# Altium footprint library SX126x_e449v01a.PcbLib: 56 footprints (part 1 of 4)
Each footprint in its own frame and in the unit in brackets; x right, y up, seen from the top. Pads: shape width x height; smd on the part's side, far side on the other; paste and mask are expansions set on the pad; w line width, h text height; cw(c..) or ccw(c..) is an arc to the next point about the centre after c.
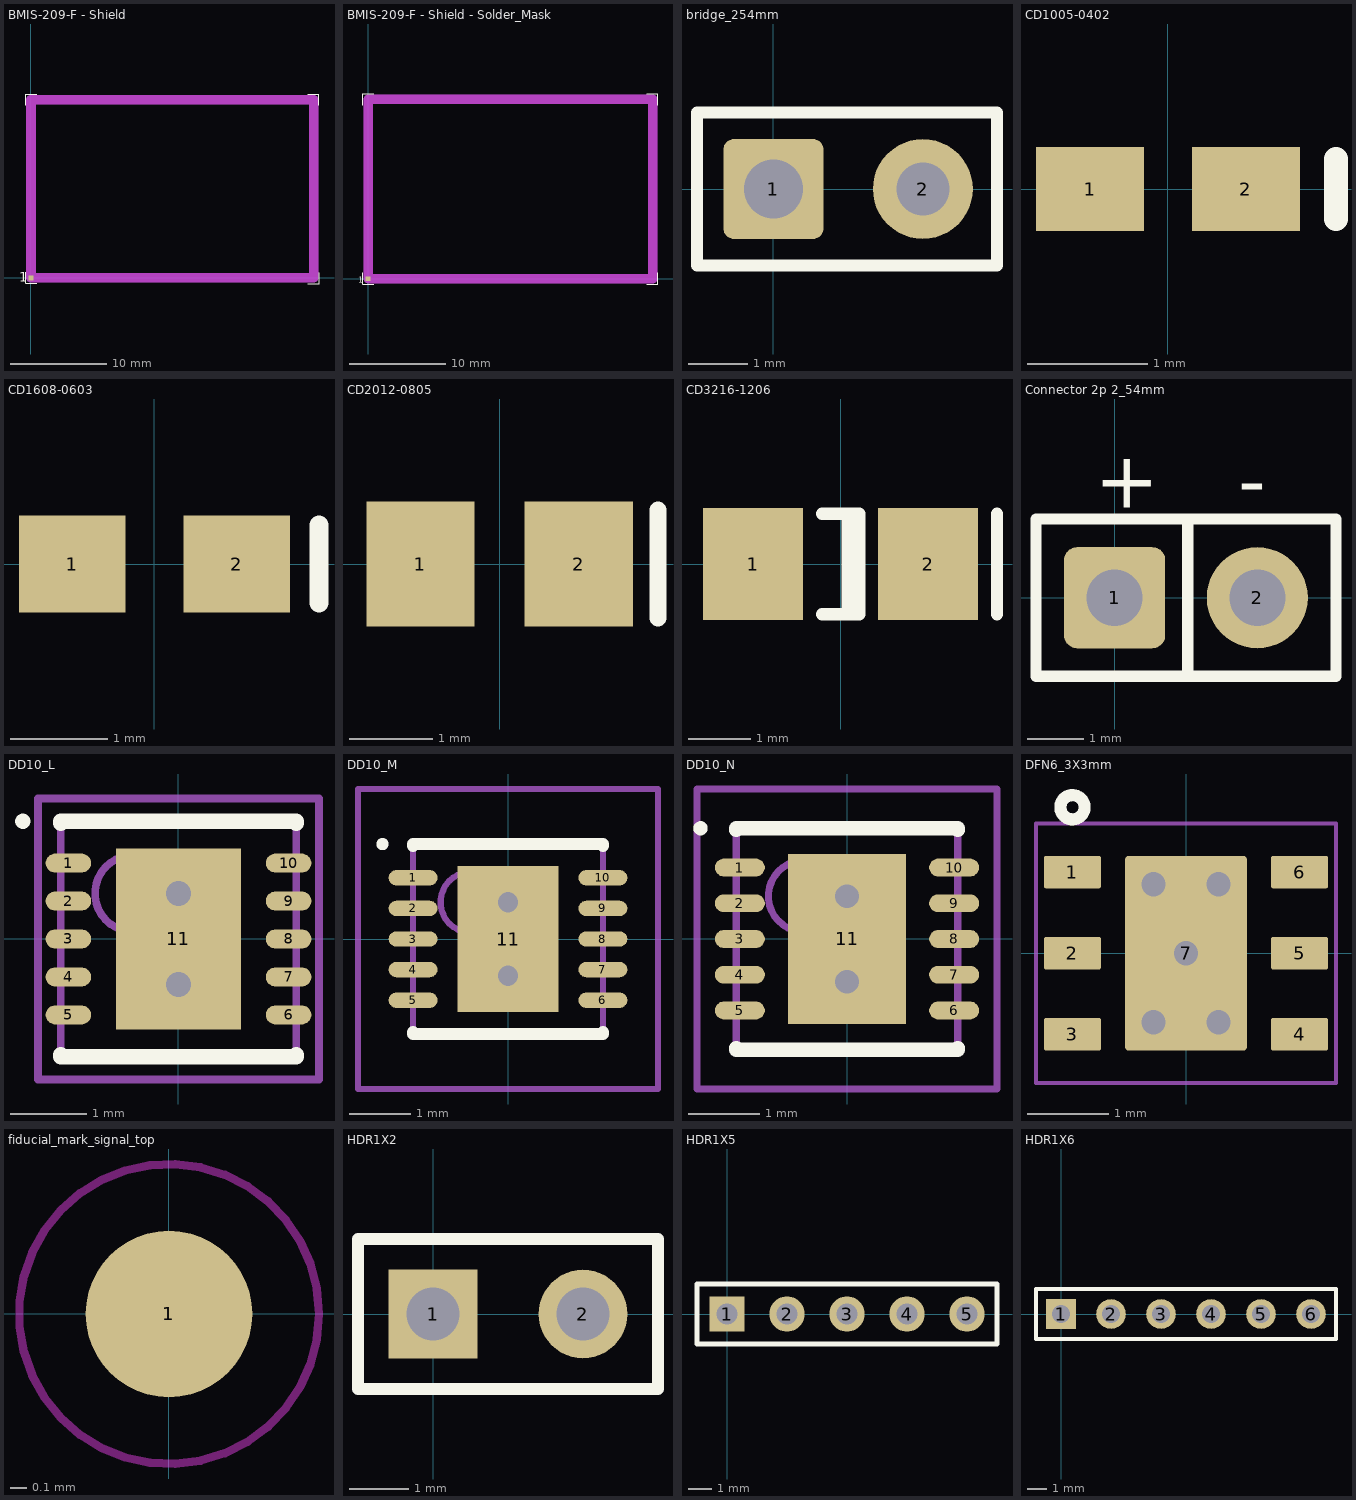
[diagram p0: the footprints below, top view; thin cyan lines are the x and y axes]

## BMIS-209-F - Shield [mm] "BMIS-209-F EMI Gasket - modif SolderMask - Standard Surface Mount Shields -  Laird Technologies"
height 6.5
pads (1):
  rect 0.5x0.5 smd paste-1 mask+0.05: 1(0,0)
Top Overlay:
  lines w0.1: -0.55,0.6 -0.55,-0.55 0.6,-0.55 ; -0.55,18 -0.55,19.15 0.6,19.15 ; 28.9,-0.6 30.05,-0.6 30.05,0.55 ; 28.9,19.15 30.05,19.15 30.05,18
  text "1" at -1.25,-0.4 h1
Top Paste:
  region: 4.35,0.6 4.35,-0.4 -0.4,-0.4 -0.4,0.6
  region: 7.1,0.6 10.3,0.6 10.3,-0.4 7.1,-0.4
  region: 13.1,0.6 16.35,0.6 16.35,-0.4 13.1,-0.4
  region: 19.1,0.6 22.3,0.6 22.3,-0.4 19.1,-0.4
  region: 25.1,0.55 29.9,0.55 29.9,-0.45 25.1,-0.45
  region: -0.4,4.6 0.6,4.6 0.6,-0.4 -0.4,-0.4
  region: -0.4,10.9 0.6,10.9 0.6,7.7 -0.4,7.7
  region: -0.4,13.7 -0.4,19 0.6,19 0.6,13.7
  region: 28.9,13.65 28.9,18.95 29.9,18.95 29.9,13.65
  region: 28.9,10.85 29.9,10.85 29.9,7.65 28.9,7.65
  region: 28.9,4.85 29.9,4.85 29.9,-0.45 28.9,-0.45
  region: 25.1,19 29.9,19 29.9,18 25.1,18
  region: 19.1,19 22.3,19 22.3,18 19.1,18
  region: 13.1,19 16.35,19 16.35,18 13.1,18
  region: 7.1,19 10.3,19 10.3,18 7.1,18
  region: 4.35,19 4.35,18 -0.4,18 -0.4,19
Top Solder:
  region: 4.35,18 -0.4,18 -0.4,19 4.35,19
  region: 10.3,18 7.1,18 7.1,19 10.3,19
  region: 16.35,18 13.1,18 13.1,19 16.35,19
  region: 29.9,18 25.1,18 25.1,19 29.9,19
  region: 22.3,18 19.1,18 19.1,19 22.3,19
  region: 22.3,-0.4 19.1,-0.4 19.1,0.6 22.3,0.6
  region: 29.9,-0.45 25.1,-0.45 25.1,0.55 29.9,0.55
  region: 16.35,-0.4 13.1,-0.4 13.1,0.6 16.35,0.6
  region: 10.3,-0.4 7.1,-0.4 7.1,0.6 10.3,0.6
  region: 4.35,-0.4 -0.4,-0.4 -0.4,0.6 4.35,0.6
  region: -0.4,13.7 -0.4,19 0.6,19 0.6,13.7
  region: -0.4,7.7 -0.4,10.9 0.6,10.9 0.6,7.7
  region: -0.4,-0.4 -0.4,4.6 0.6,4.6 0.6,-0.4
  region: 28.9,-0.45 28.9,4.85 29.9,4.85 29.9,-0.45
  region: 28.9,7.65 28.9,10.85 29.9,10.85 29.9,7.65
  region: 28.9,13.65 28.9,18.95 29.9,18.95 29.9,13.65
Mechanical 15 keep-out:
  lines w1: 0,0 0,18.6 29.5,18.6 29.5,0 0,0
3D body: height 0.8, standoff 0.2, extent -0.3,-0.3 0.3,0.3

## BMIS-209-F - Shield - Solder_Mask [mm] "BMIS-209-F EMI Gasket - modif SolderMask - Standard Surface Mount Shields -  Laird Technologies"
height 6.5
pads (1):
  rect 0.5x0.5 smd paste-1 mask+0.05: 1(0,0)
Top Overlay:
  lines w0.1: -0.55,0.6 -0.55,-0.55 0.6,-0.55 ; -0.55,18 -0.55,19.15 0.6,19.15 ; 28.9,-0.55 30.05,-0.55 30.05,0.6 ; 28.9,19.15 30.05,19.15 30.05,18
  text "1" at -1.05,-0.4 h0.6
Top Paste:
  region: 29.9,19 29.9,18 -0.4,18 -0.4,19
  region: 28.9,5.6 29.9,5.6 29.9,-0.4 28.9,-0.4
  region: 28.9,6.65 28.9,19 29.9,19 29.9,6.65
  region: -0.4,4.6 0.6,4.6 0.6,-0.4 -0.4,-0.4
  region: 29.9,0.6 29.9,-0.4 -0.4,-0.4 -0.4,0.6
  region: -0.4,7.7 -0.4,19 0.6,19 0.6,7.7
Top Solder:
  region: -0.4,7.7 -0.4,19 0.6,19 0.6,7.7
  region: 29.9,0.6 29.9,-0.4 -0.4,-0.4 -0.4,0.6
  region: -0.4,4.6 0.6,4.6 0.6,-0.4 -0.4,-0.4
  region: 28.9,6.65 28.9,19 29.9,19 29.9,6.65
  region: 28.9,5.6 29.9,5.6 29.9,-0.4 28.9,-0.4
  region: 29.9,19 29.9,18 -0.4,18 -0.4,19
Mechanical 15 keep-out:
  lines w1: 0,0 29.5,0 29.5,18.6 0,18.6 0,0
3D body: height 0.8, standoff 0.2, extent -0.3,-0.3 0.3,0.3

## bridge_254mm [mm] "Generic Bridge 2.54mm, 2 Leads 0.9mm;"
height 1
pads (2):
  rrect20% 1.7x1.7 hole 1 paste+0 mask+0.05: 1(0,0)
  round 1.7 hole 0.9 paste+0 mask+0.05: 2(2.54,0)
Top Overlay:
  lines w0.2: -1.3,-1.3 3.8,-1.3 3.8,1.3 -1.3,1.3 -1.3,-1.3

## CD1005-0402 [mm] "Chip Diode; Body 1.0 x 0.5 mm (LxW typ)"
height 0.6
pads (2):
  rect 0.9x0.7 smd mask+0.05: 1(-0.65,0) 2(0.65,0)
Top Overlay:
  lines w0.2: 1.4,-0.25 1.4,0.25

## CD1608-0603 [mm] "Chip Diode; Body 1.6 x 0.8 mm (LxW typ)"
height 0.85
pads (2):
  rect 1.1x1 smd mask+0.05: 1(-0.85,0) 2(0.85,0)
Top Overlay:
  lines w0.2: 1.7,-0.4 1.7,0.4

## CD2012-0805 [mm] "Chip Diode; Body 2.0 x 1.3 mm (LxW typ)"
height 1.1
pads (2):
  rect 1.3x1.5 smd mask+0.05: 1(-0.95,0) 2(0.95,0)
Top Overlay:
  lines w0.2: 1.9,-0.65 1.9,0.65

## CD3216-1206 [mm] "Chip Diode; Body 3.2 x 1.6 mm (LxW typ)"
height 1.35
pads (2):
  rect 1.6x1.8 smd mask+0.05: 1(-1.4,0) 2(1.4,0)
Top Overlay:
  lines w0.2: -0.3,-0.8 0.3,-0.8 0.3,0.8 -0.3,0.8 ; 0.11,-0.8 0.11,0.8 ; 2.5,-0.8 2.5,0.8

## Connector 2p 2_54mm [mm] "Generic connector 2.54mm, 2 Leads 1mm;"
height 1
pads (2):
  rrect25% 1.8x1.8 hole 1 paste+0 mask+0.05: 1(0,0)
  round 1.8 hole 1 paste+0 mask+0.05: 2(2.54,0)
Top Overlay:
  lines w0.2: 1.3,-1.4 1.3,1.4 ; -1.4,-1.4 3.94,-1.4 3.94,1.4 -1.4,1.4 -1.4,-1.4
  text "+" at -0.35,1.6 h1
  text "-" at 2.2,1.6 h1

## DD10_L [mm] "SON, 10-Leads, Body 3x3 mm, Pitch 0.5mm, IPC High Density"
height 0.8
pads (11):
  oval 0.6x0.25 smd: 1(-1.45,1) 2(-1.45,0.5) 3(-1.45,0) 4(-1.45,-0.5) 5(-1.45,-1) 6(1.45,-1) 7(1.45,-0.5) 8(1.45,0) 9(1.45,0.5) 10(1.45,1)
  rect 1.65x2.38 smd: 11(0,0)
via 0,0.6 diameter 0.66 hole 0.33
via 0,-0.6 diameter 0.66 hole 0.33
Top Overlay:
  circle w0.1: c-2.05,1.55 r0.05
  lines w0.2: -1.55,-1.525 -1.55,-1.55 1.55,-1.55 1.55,-1.525 ; -1.55,1.525 -1.55,1.55 1.55,1.55 1.55,1.525
Mechanical 13:
  circle w0.1: c-0.6,0.6 r0.5
  lines w0.1: -1.55,-1.55 1.55,-1.55 1.55,1.55 -1.55,1.55 -1.55,-1.55
Mechanical 15:
  lines w0.1: -0.5,0 0.5,0 ; 0,-0.5 0,0.5 ; -1.85,-1.85 1.85,-1.85 1.85,1.85 -1.85,1.85 -1.85,-1.85
3D body: height 0.8, standoff 0, extent -1.55,-1.55 1.55,1.55

## DD10_M [mm] "SON, 10-Leads, Body 3x3 mm, Pitch 0.5mm, IPC Low Density"
height 0.8
pads (11):
  oval 0.8x0.25 smd: 1(-1.55,1) 2(-1.55,0.5) 3(-1.55,0) 4(-1.55,-0.5) 5(-1.55,-1) 6(1.55,-1) 7(1.55,-0.5) 8(1.55,0) 9(1.55,0.5) 10(1.55,1)
  rect 1.65x2.38 smd: 11(0,0)
via 0,0.6 diameter 0.66 hole 0.33
via 0,-0.6 diameter 0.66 hole 0.33
Top Overlay:
  circle w0.1: c-2.05,1.55 r0.05
  lines w0.2: -1.55,-1.525 -1.55,-1.55 1.55,-1.55 1.55,-1.525 ; -1.55,1.525 -1.55,1.55 1.55,1.55 1.55,1.525
Mechanical 13:
  circle w0.1: c-0.6,0.6 r0.5
  lines w0.1: -1.55,-1.55 1.55,-1.55 1.55,1.55 -1.55,1.55 -1.55,-1.55
Mechanical 15:
  lines w0.1: -0.5,0 0.5,0 ; 0,-0.5 0,0.5 ; -2.45,-2.45 2.45,-2.45 2.45,2.45 -2.45,2.45 -2.45,-2.45
3D body: height 0.8, standoff 0, extent -1.55,-1.55 1.55,1.55

## DD10_N [mm] "SON, 10-Leads, Body 3x3 mm, Pitch 0.5mm, IPC Medium Density"
height 0.8
pads (11):
  oval 0.7x0.25 smd: 1(-1.5,1) 2(-1.5,0.5) 3(-1.5,0) 4(-1.5,-0.5) 5(-1.5,-1) 6(1.5,-1) 7(1.5,-0.5) 8(1.5,0) 9(1.5,0.5) 10(1.5,1)
  rect 1.65x2.38 smd: 11(0,0)
via 0,0.6 diameter 0.66 hole 0.33
via 0,-0.6 diameter 0.66 hole 0.33
Top Overlay:
  circle w0.1: c-2.05,1.55 r0.05
  lines w0.2: -1.55,-1.525 -1.55,-1.55 1.55,-1.55 1.55,-1.525 ; -1.55,1.525 -1.55,1.55 1.55,1.55 1.55,1.525
Mechanical 13:
  circle w0.1: c-0.6,0.6 r0.5
  lines w0.1: -1.55,-1.55 1.55,-1.55 1.55,1.55 -1.55,1.55 -1.55,-1.55
Mechanical 15:
  lines w0.1: -0.5,0 0.5,0 ; 0,-0.5 0,0.5 ; -2.1,-2.1 2.1,-2.1 2.1,2.1 -2.1,2.1 -2.1,-2.1
3D body: height 0.8, standoff 0, extent -1.55,-1.55 1.55,1.55

## DFN6_3X3mm [mm] "6 Leads, Body 3x3mm, pitch 1.0mm, DFN6"
height 1
pads (7):
  rrect10% 0.7x0.4 smd paste+0 mask+0.05: 1(-1.4,1) 2(-1.4,0) 3(-1.4,-1) 4(1.4,-1) 5(1.4,0) 6(1.4,1)
  rrect5% 1.5x2.4 smd paste-0.2 mask+0.05: 7(0,0)
via 0.4,-0.85 diameter 0.6 hole 0.3
via -0.4,0.85 diameter 0.6 hole 0.3
via -0.4,-0.85 diameter 0.6 hole 0.3
via 0.4,0.85 diameter 0.6 hole 0.3
via 0,0 diameter 0.6 hole 0.3
Top Overlay:
  circle w0.15: c-1.4,1.8 r0.15
Top Paste:
  region: 0.15,0.15 -0.15,0.15 -0.15,-0.15 0.15,-0.15
Mechanical 15:
  lines w0.05: -1.85,-1.6 1.85,-1.6 1.85,1.6 -1.85,1.6 -1.85,-1.6
3D body: height 1, standoff 0, extent -1.5,-1.5 1.5,1.5

## fiducial_mark_signal_top [mm] "Fiducial mark for automatic assembly"
height 1
pads (1):
  round 1 smd paste-2 mask+0.5: 1(0,0)
Top Layer keep-out:
  circle w0.05: c0,0 r0.9

## HDR1X2 [mm] "Connector; Header; 2 Position"
pads (2):
  rect 1.5x1.5 hole 0.9: 1(0,0)
  round 1.5 hole 0.9: 2(2.54,0)
Top Overlay:
  lines w0.2: -1.27,-1.27 -1.27,1.27 3.81,1.27 3.81,-1.27 -1.27,-1.27

## HDR1X5 [mm] "Connector; Header; 5 Position"
pads (5):
  rect 1.5x1.5 hole 0.9: 1(0,0)
  round 1.5 hole 0.9: 2(2.54,0) 3(5.08,0) 4(7.62,0) 5(10.16,0)
Top Overlay:
  lines w0.2: -1.27,-1.27 -1.27,1.27 11.43,1.27 11.43,-1.27 -1.27,-1.27

## HDR1X6 [mm] "Connector; Header; 6 Position"
pads (6):
  rect 1.5x1.5 hole 0.9: 1(0,0)
  round 1.5 hole 0.9: 2(2.54,0) 3(5.08,0) 4(7.62,0) 5(10.16,0) 6(12.7,0)
Top Overlay:
  lines w0.2: -1.27,-1.27 13.97,-1.27 13.97,1.27 -1.27,1.27 -1.27,-1.27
